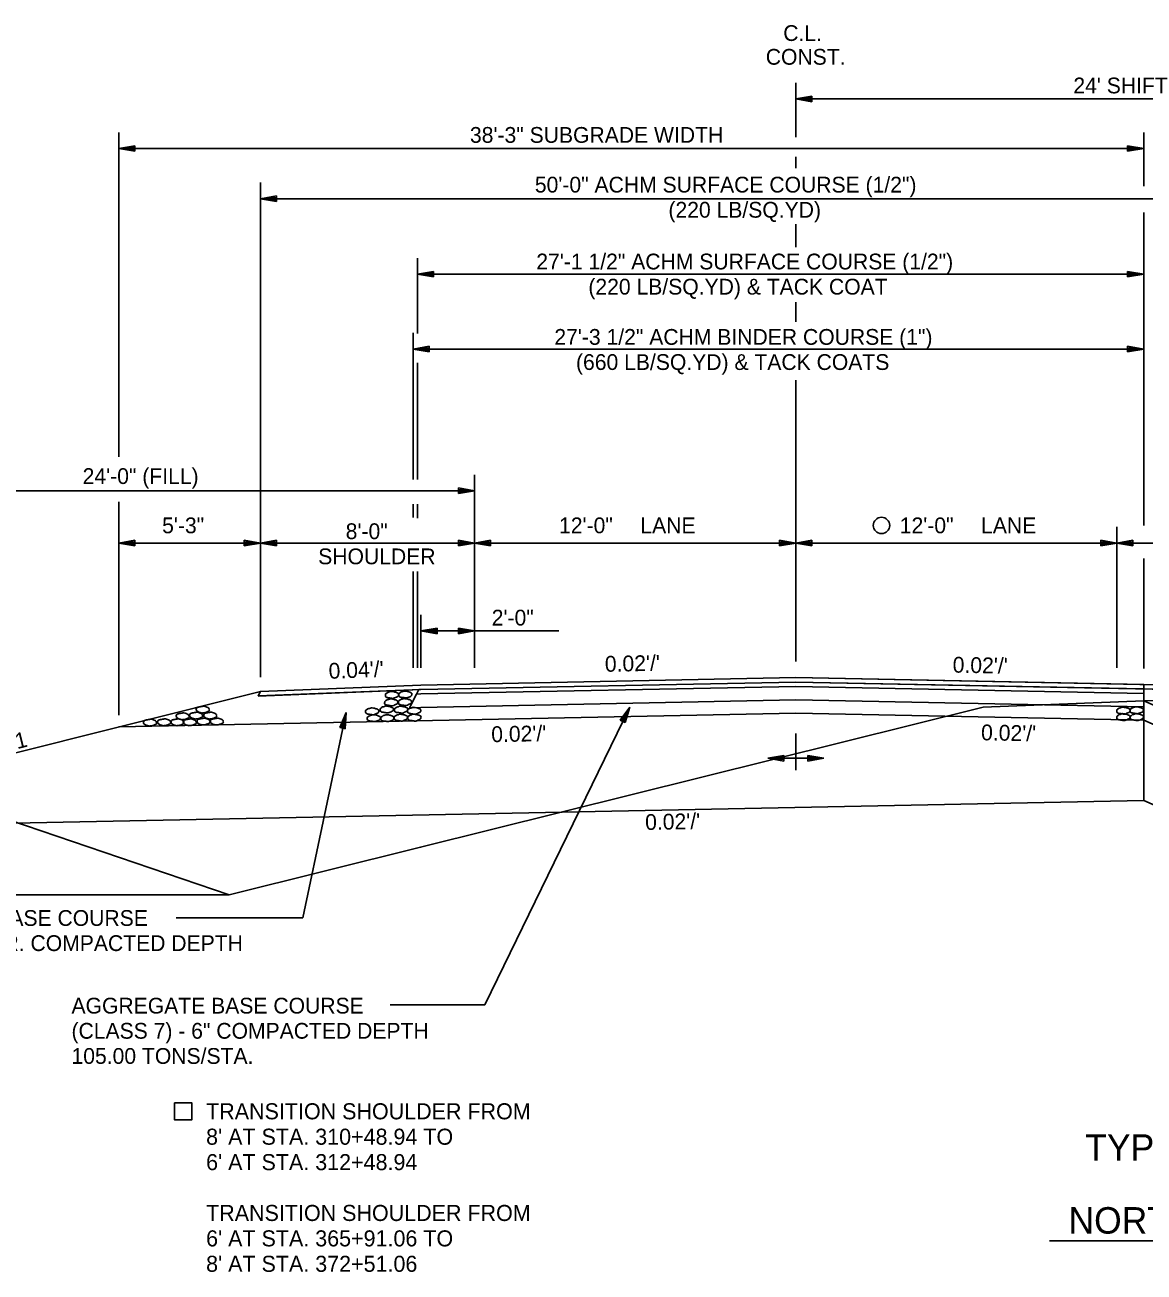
# Model space of a CAD drawing. Extents: x 1398565 to 1398920, y 1968324 to 1968581.
# Drawn here: x 1398801.17 to 1398842.98, y 1968479.92 to 1968526.53 of the extents above; entities that cross this region are included whole.
import ezdxf

# ---------------------------------------------------------------- set-up
doc = ezdxf.new("R2010")
doc.units = 0
for name, color, linetype in [('1', 7, 'Continuous'), ('10', 7, 'Continuous'), ('19', 7, 'Continuous'), ('42', 7, 'Continuous'), ('7', 7, 'Continuous'), ('Level 1', 7, 'Continuous')]:
    doc.layers.add(name, color=color, linetype=linetype)

# ---------------------------------------------------------------- blocks, each defined once
blk = doc.blocks.new('ROCKS')
at = {"layer": '1'}
blk.add_spline([(0.013, 0.06), (0.053, 0.053), (0.107, 0.033), (0.133, 0.013), (0.133, -0.007), (0.12, -0.033), (0.107, -0.04), (0.073, -0.053), (0.033, -0.067), (0.013, -0.067), (-0.02, -0.06), (-0.06, -0.053), (-0.087, -0.047), (-0.113, -0.02), (-0.113, -0.007), (-0.107, 0.02), (-0.087, 0.033), (-0.067, 0.047), (-0.033, 0.053), (-0.02, 0.06), (0.013, 0.06)], degree=3, dxfattribs=at)
blk = doc.blocks.new('4TO1 ABC')
at = {"layer": '1', "xscale": 0.1312491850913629, "yscale": 0.1312491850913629, "rotation": 180}
for p in [(0.00175, -0.00875), (-0.03325, -0.0385), (-0.016625, -0.023625), (0, -0.0385), (0.018375, -0.023625), (0.051625, -0.025375), (0.034125, -0.04025), (0.06475, -0.04025), (0.098, -0.04025), (0.133, -0.041125)]:
    blk.add_blockref('ROCKS', p, dxfattribs=at)

msp = doc.modelspace()

# ---------------------------------------------------------------- linework, layer by layer
at = {"layer": '10'}
msp.add_lwpolyline([(1398806.767, 1968486.248), (1398807.408, 1968486.248), (1398807.408, 1968485.607), (1398806.767, 1968485.607)], close=True, dxfattribs=at)
msp.add_circle((1398833.174, 1968507.826), 0.306, dxfattribs=at)
at = {"layer": '19'}
for p, q in [((1398830.569, 1968523.875), (1398829.969, 1968523.77)), ((1398853.969, 1968523.77), (1398829.969, 1968523.77)), ((1398829.969, 1968523.77), (1398830.569, 1968523.665)), ((1398830.569, 1968523.82), (1398830.129, 1968523.785)), ((1398830.129, 1968523.755), (1398830.569, 1968523.715)), ((1398830.569, 1968523.665), (1398830.569, 1968523.875)), ((1398804.684, 1968510.387), (1398804.684, 1968522.515)), ((1398842.969, 1968520.503), (1398842.969, 1968522.515)), ((1398805.284, 1968522.02), (1398804.684, 1968521.915)), ((1398842.969, 1968521.915), (1398804.684, 1968521.915)), ((1398804.684, 1968521.915), (1398805.284, 1968521.81)), ((1398805.284, 1968521.965), (1398804.844, 1968521.93)), ((1398804.844, 1968521.9), (1398805.284, 1968521.86)), ((1398805.284, 1968521.81), (1398805.284, 1968522.02)), ((1398842.369, 1968522.02), (1398842.369, 1968521.81)), ((1398842.969, 1968521.915), (1398842.369, 1968522.02)), ((1398842.809, 1968521.93), (1398842.369, 1968521.965)), ((1398842.369, 1968521.81), (1398842.969, 1968521.915)), ((1398842.369, 1968521.86), (1398842.809, 1968521.9)), ((1398809.969, 1968502.154), (1398809.969, 1968520.64)), ((1398810.569, 1968520.145), (1398809.969, 1968520.04)), ((1398809.969, 1968520.04), (1398859.969, 1968520.04)), ((1398809.969, 1968520.04), (1398810.569, 1968519.935)), ((1398810.569, 1968520.09), (1398810.129, 1968520.055)), ((1398810.129, 1968520.025), (1398810.569, 1968519.985)), ((1398810.569, 1968519.935), (1398810.569, 1968520.145)), ((1398842.969, 1968507.82), (1398842.969, 1968519.52)), ((1398815.842, 1968515.006), (1398815.842, 1968517.818)), ((1398816.442, 1968517.323), (1398815.842, 1968517.218)), ((1398815.842, 1968517.218), (1398816.442, 1968517.113)), ((1398815.842, 1968517.218), (1398842.969, 1968517.218)), ((1398816.442, 1968517.268), (1398816.002, 1968517.233)), ((1398816.002, 1968517.203), (1398816.442, 1968517.163)), ((1398816.442, 1968517.113), (1398816.442, 1968517.323)), ((1398842.369, 1968517.323), (1398842.369, 1968517.113)), ((1398842.969, 1968517.218), (1398842.369, 1968517.323)), ((1398842.809, 1968517.233), (1398842.369, 1968517.268)), ((1398842.369, 1968517.113), (1398842.969, 1968517.218)), ((1398842.369, 1968517.163), (1398842.809, 1968517.203)), ((1398815.672, 1968509.54), (1398815.672, 1968515.02)), ((1398816.272, 1968514.525), (1398815.672, 1968514.42)), ((1398815.672, 1968514.42), (1398842.969, 1968514.42)), ((1398815.672, 1968514.42), (1398816.272, 1968514.315)), ((1398816.272, 1968514.47), (1398815.832, 1968514.435)), ((1398815.832, 1968514.405), (1398816.272, 1968514.365)), ((1398816.272, 1968514.315), (1398816.272, 1968514.525)), ((1398842.369, 1968514.525), (1398842.369, 1968514.315)), ((1398842.969, 1968514.42), (1398842.369, 1968514.525)), ((1398842.809, 1968514.435), (1398842.369, 1968514.47)), ((1398842.369, 1968514.315), (1398842.969, 1968514.42)), ((1398842.369, 1968514.365), (1398842.809, 1968514.405)), ((1398815.842, 1968509.54), (1398815.842, 1968513.9)), ((1398817.969, 1968502.501), (1398817.969, 1968509.724)), ((1398793.969, 1968509.124), (1398817.969, 1968509.124)), ((1398817.369, 1968509.019), (1398817.369, 1968509.229)), ((1398817.369, 1968509.229), (1398817.969, 1968509.124)), ((1398817.369, 1968509.174), (1398817.809, 1968509.139)), ((1398817.969, 1968509.124), (1398817.369, 1968509.019)), ((1398804.684, 1968500.741), (1398804.684, 1968508.71)), ((1398817.809, 1968509.109), (1398817.369, 1968509.069)), ((1398815.672, 1968508.127), (1398815.672, 1968508.618)), ((1398815.842, 1968508.096), (1398815.842, 1968508.618)), ((1398841.969, 1968502.501), (1398841.969, 1968507.77)), ((1398804.684, 1968507.17), (1398805.284, 1968507.275)), ((1398805.284, 1968507.275), (1398805.284, 1968507.065)), ((1398809.369, 1968507.275), (1398809.369, 1968507.065)), ((1398809.969, 1968507.17), (1398809.369, 1968507.275)), ((1398809.969, 1968507.17), (1398810.569, 1968507.275)), ((1398810.569, 1968507.275), (1398810.569, 1968507.065)), ((1398817.369, 1968507.065), (1398817.369, 1968507.275)), ((1398817.369, 1968507.275), (1398817.969, 1968507.17)), ((1398817.969, 1968507.17), (1398818.569, 1968507.275)), ((1398818.569, 1968507.275), (1398818.569, 1968507.065)), ((1398829.369, 1968507.065), (1398829.369, 1968507.275)), ((1398829.369, 1968507.275), (1398829.969, 1968507.17)), ((1398829.969, 1968507.17), (1398830.569, 1968507.275)), ((1398830.569, 1968507.275), (1398830.569, 1968507.065)), ((1398841.369, 1968507.065), (1398841.369, 1968507.275)), ((1398841.369, 1968507.275), (1398841.969, 1968507.17)), ((1398841.969, 1968507.17), (1398842.569, 1968507.275)), ((1398842.569, 1968507.275), (1398842.569, 1968507.065)), ((1398859.969, 1968507.17), (1398804.684, 1968507.17)), ((1398805.284, 1968507.065), (1398804.684, 1968507.17)), ((1398804.844, 1968507.185), (1398805.284, 1968507.22)), ((1398805.284, 1968507.115), (1398804.844, 1968507.155)), ((1398809.809, 1968507.185), (1398809.369, 1968507.22)), ((1398809.369, 1968507.065), (1398809.969, 1968507.17)), ((1398809.369, 1968507.115), (1398809.809, 1968507.155)), ((1398810.569, 1968507.065), (1398809.969, 1968507.17)), ((1398810.129, 1968507.185), (1398810.569, 1968507.22)), ((1398810.569, 1968507.115), (1398810.129, 1968507.155)), ((1398817.369, 1968507.22), (1398817.809, 1968507.185)), ((1398817.969, 1968507.17), (1398817.369, 1968507.065)), ((1398817.809, 1968507.155), (1398817.369, 1968507.115)), ((1398818.569, 1968507.065), (1398817.969, 1968507.17)), ((1398818.129, 1968507.185), (1398818.569, 1968507.22)), ((1398818.569, 1968507.115), (1398818.129, 1968507.155)), ((1398829.369, 1968507.22), (1398829.809, 1968507.185)), ((1398829.969, 1968507.17), (1398829.369, 1968507.065)), ((1398829.809, 1968507.155), (1398829.369, 1968507.115)), ((1398830.569, 1968507.065), (1398829.969, 1968507.17)), ((1398830.129, 1968507.185), (1398830.569, 1968507.22)), ((1398830.569, 1968507.115), (1398830.129, 1968507.155)), ((1398841.369, 1968507.22), (1398841.809, 1968507.185)), ((1398841.969, 1968507.17), (1398841.369, 1968507.065)), ((1398841.809, 1968507.155), (1398841.369, 1968507.115)), ((1398842.569, 1968507.065), (1398841.969, 1968507.17)), ((1398842.129, 1968507.185), (1398842.569, 1968507.22)), ((1398842.569, 1968507.115), (1398842.129, 1968507.155)), ((1398842.969, 1968502.481), (1398842.969, 1968506.591)), ((1398815.672, 1968502.501), (1398815.672, 1968506.1)), ((1398815.842, 1968502.501), (1398815.842, 1968506.1)), ((1398815.969, 1968502.501), (1398815.969, 1968504.482)), ((1398815.969, 1968503.882), (1398816.569, 1968503.987)), ((1398815.969, 1968503.882), (1398821.116, 1968503.882)), ((1398816.569, 1968503.777), (1398815.969, 1968503.882)), ((1398816.129, 1968503.897), (1398816.569, 1968503.932)), ((1398816.569, 1968503.827), (1398816.129, 1968503.867)), ((1398816.569, 1968503.987), (1398816.569, 1968503.777)), ((1398817.369, 1968503.777), (1398817.369, 1968503.987)), ((1398817.369, 1968503.987), (1398817.969, 1968503.882)), ((1398817.369, 1968503.932), (1398817.809, 1968503.897)), ((1398817.969, 1968503.882), (1398817.369, 1968503.777)), ((1398817.809, 1968503.867), (1398817.369, 1968503.827)), ((1398829.969, 1968502.141), (1398815.969, 1968501.861)), ((1398829.969, 1968502.141), (1398855.969, 1968501.621)), ((1398815.969, 1968501.694), (1398809.884, 1968501.451)), ((1398815.969, 1968501.861), (1398809.969, 1968501.621)), ((1398815.884, 1968501.691), (1398815.799, 1968501.521)), ((1398829.969, 1968501.974), (1398815.969, 1968501.694)), ((1398829.969, 1968501.808), (1398815.969, 1968501.528)), ((1398829.969, 1968501.974), (1398855.969, 1968501.454)), ((1398829.969, 1968501.808), (1398842.969, 1968501.548)), ((1398842.969, 1968501.548), (1398829.969, 1968501.808)), ((1398842.969, 1968501.881), (1398842.969, 1968500.256)), ((1398809.969, 1968501.621), (1398793.969, 1968497.621)), ((1398809.969, 1968501.621), (1398809.884, 1968501.451)), ((1398815.799, 1968501.521), (1398815.544, 1968501.01)), ((1398815.969, 1968501.528), (1398815.799, 1968501.521)), ((1398829.969, 1968501.307), (1398815.969, 1968501.027)), ((1398829.969, 1968501.307), (1398842.969, 1968501.047)), ((1398829.969, 1968501.307), (1398842.969, 1968501.047)), ((1398842.969, 1968501.047), (1398842.969, 1968501.548)), ((1398842.969, 1968501.548), (1398842.969, 1968501.548)), ((1398842.969, 1968501.274), (1398845.712, 1968500.064)), ((1398829.969, 1968500.805), (1398804.684, 1968500.3)), ((1398811.552, 1968493.162), (1398813.172, 1968500.835)), ((1398813.172, 1968500.835), (1398812.937, 1968500.272)), ((1398813.141, 1968500.228), (1398813.172, 1968500.835)), ((1398815.969, 1968501.027), (1398815.544, 1968501.01)), ((1398818.351, 1968489.903), (1398823.771, 1968501.037)), ((1398823.771, 1968501.037), (1398823.408, 1968500.548)), ((1398823.689, 1968500.9), (1398823.456, 1968500.527)), ((1398823.551, 1968500.478), (1398823.714, 1968500.887)), ((1398823.595, 1968500.456), (1398823.771, 1968501.037)), ((1398829.969, 1968500.805), (1398842.969, 1968500.545)), ((1398812.937, 1968500.272), (1398813.141, 1968500.228)), ((1398813.125, 1968500.682), (1398812.99, 1968500.264)), ((1398813.093, 1968500.239), (1398813.152, 1968500.676)), ((1398823.408, 1968500.548), (1398823.595, 1968500.456)), ((1398842.969, 1968500.545), (1398845.712, 1968499.335)), ((1398842.969, 1968500.256), (1398842.969, 1968497.545)), ((1398842.969, 1968497.545), (1398790.6, 1968496.498)), ((1398842.969, 1968497.545), (1398845.712, 1968496.335)), ((1398806.824, 1968493.162), (1398811.552, 1968493.162)), ((1398814.823, 1968489.903), (1398818.351, 1968489.903)), ((1398839.453, 1968481.09), (1398868.433, 1968481.09))]:
    msp.add_line(p, q, dxfattribs=at)
for points in [[(1398809.887, 1968501.456), (1398815.969, 1968501.694), (1398829.969, 1968501.974), (1398855.969, 1968501.454), (1398860.054, 1968501.291), (1398859.969, 1968501.461), (1398855.969, 1968501.621), (1398829.969, 1968502.141), (1398815.969, 1968501.861), (1398809.969, 1968501.621)], [(1398815.884, 1968501.691), (1398815.799, 1968501.521), (1398815.969, 1968501.528), (1398829.969, 1968501.808), (1398842.969, 1968501.548), (1398842.969, 1968501.714), (1398829.969, 1968501.974), (1398815.969, 1968501.694)]]:
    msp.add_lwpolyline(points, close=True, dxfattribs=at)
for points in [[(1398829.969, 1968501.808), (1398815.969, 1968501.528), (1398815.799, 1968501.521), (1398815.544, 1968501.01)], [(1398815.544, 1968501.01), (1398815.969, 1968501.027), (1398829.969, 1968501.307)]]:
    msp.add_lwpolyline(points, dxfattribs=at)
at = {"layer": '42'}
for p, q in [((1398829.969, 1968500.046), (1398829.969, 1968498.675)), ((1398829.522, 1968499.232), (1398828.922, 1968499.127)), ((1398828.922, 1968499.127), (1398829.522, 1968499.022)), ((1398828.922, 1968499.127), (1398831.017, 1968499.127)), ((1398829.522, 1968499.177), (1398829.082, 1968499.142)), ((1398829.082, 1968499.112), (1398829.522, 1968499.072)), ((1398829.522, 1968499.022), (1398829.522, 1968499.232)), ((1398830.417, 1968499.022), (1398830.417, 1968499.232)), ((1398830.417, 1968499.232), (1398831.017, 1968499.127)), ((1398830.417, 1968499.177), (1398830.857, 1968499.142)), ((1398831.017, 1968499.127), (1398830.417, 1968499.022)), ((1398830.857, 1968499.112), (1398830.417, 1968499.072))]:
    msp.add_line(p, q, dxfattribs=at)
for points in [[(1398766.028, 1968494.02), (1398808.809, 1968494.02), (1398815.956, 1968495.8), (1398836.969, 1968501.034), (1398842.969, 1968501.274)], [(1398842.969, 1968501.274), (1398853.969, 1968501.494)], [(1398808.809, 1968494.02), (1398800.009, 1968497.014), (1398796.149, 1968497.696), (1398791.889, 1968498.539), (1398775.39, 1968500.448), (1398764.214, 1968500.493)]]:
    msp.add_lwpolyline(points, dxfattribs=at)
at = {"layer": '7'}
for p, q in [((1398829.969, 1968522.345), (1398829.969, 1968524.37)), ((1398829.969, 1968521.178), (1398829.969, 1968521.608)), ((1398829.969, 1968518.23), (1398829.969, 1968519.09)), ((1398829.969, 1968515.436), (1398829.969, 1968516.173)), ((1398829.969, 1968502.741), (1398829.969, 1968513.255))]:
    msp.add_line(p, q, dxfattribs=at)

# ---------------------------------------------------------------- block references
at = {"layer": '19', "xscale": 14.999970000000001, "yscale": -14.999970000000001, "rotation": 180}
msp.add_blockref('4TO1 ABC', (1398807.824, 1968501.068), dxfattribs=at)
at = {"layer": 'Level 1', "xscale": 2.011654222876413, "yscale": 2.011654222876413, "rotation": 1.8263814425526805}
for p in [(1398814.838, 1968501.218), (1398814.865, 1968501.497), (1398815.35, 1968501.23), (1398815.363, 1968501.512), (1398814.127, 1968500.883), (1398814.186, 1968500.627), (1398814.67, 1968500.953), (1398814.691, 1968500.627), (1398815.196, 1968500.648), (1398815.203, 1968500.948), (1398815.694, 1968500.905), (1398815.7, 1968500.647), (1398842.19, 1968500.91), (1398842.19, 1968500.668), (1398842.688, 1968500.924), (1398842.694, 1968500.667)]:
    msp.add_blockref('ROCKS', p, dxfattribs=at)

# ---------------------------------------------------------------- texts
at = {"layer": '10'}
for s, height, rotation, p in [('24\'-0" (FILL)', 0.59001, 360, (1398803.329, 1968509.376)), ('5\'-3"', 0.59, 360, (1398806.299, 1968507.534)), ('8\'-0" ', 0.59, 360, (1398813.156, 1968507.315)), ('12\'-0" ', 0.59, 360, (1398821.127, 1968507.534)), ('LANE', 0.59, 360, (1398824.165, 1968507.534)), ('12\'-0" ', 0.59, 360, (1398833.856, 1968507.534)), ('LANE', 0.59, 360, (1398836.894, 1968507.534)), ('SHOULDER', 0.59, 360, (1398812.129, 1968506.375)), ('2\'-0"', 0.59, 360, (1398818.612, 1968504.086)), ('4:1', 0.59, 13.7364, (1398800.242, 1968499.307))]:
    msp.add_text(s, height=height, rotation=rotation, dxfattribs=at).set_placement(p)
at = {"layer": '19'}
msp.add_text('C.L.', height=0.59, dxfattribs=at).set_placement((1398829.503, 1968525.935))
for s, height, rotation, p in [('CONST.', 0.59, 360, (1398828.85, 1968525.047)), ("24' SHIFT", 0.59, 360, (1398840.341, 1968523.976)), ("0.04'/'", 0.59, 2.2906, (1398812.53, 1968502.092)), ("0.02'/'", 0.59, 1.1458, (1398822.844, 1968502.355)), ("0.02'/'", 0.59, 358.8542, (1398835.828, 1968502.328)), ("0.02'/'", 0.59, 1.1458, (1398818.6, 1968499.725)), ("0.02'/'", 0.59, 358.8542, (1398836.889, 1968499.799)), ("0.02'/'", 0.59, 1.1458, (1398824.349, 1968496.442)), ('AGGREGATE BASE COURSE', 0.59001, 360, (1398794.849, 1968492.859)), ('(CLASS 7) - VAR. COMPACTED DEPTH', 0.59001, 360, (1398794.849, 1968491.919)), ('AGGREGATE BASE COURSE', 0.59001, 360, (1398802.913, 1968489.582)), ('(CLASS 7) - 6" COMPACTED DEPTH', 0.59001, 360, (1398802.913, 1968488.642)), ('105.00 TONS/STA.', 0.59001, 360, (1398802.913, 1968487.702)), ('TYPICAL SECTION OF IMPROVEMENT', 0.98999, 360, (1398840.787, 1968484.079)), ('NORTHBOUND PASSING LANE (SITE 3)', 0.98999, 360, (1398840.16, 1968481.356))]:
    msp.add_text(s, height=height, rotation=rotation, dxfattribs=at).set_placement(p)
at = {"layer": '42'}
for s, p in [('38\'-3" SUBGRADE WIDTH', (1398817.799, 1968522.128)), ('50\'-0" ACHM SURFACE COURSE (1/2")', (1398820.223, 1968520.27)), ('(220 LB/SQ.YD)', (1398825.213, 1968519.33)), ('27\'-1 1/2" ACHM SURFACE COURSE (1/2")', (1398820.278, 1968517.396)), ('(220 LB/SQ.YD) & TACK COAT', (1398822.222, 1968516.456)), ('27\'-3 1/2" ACHM BINDER COURSE (1")', (1398820.952, 1968514.578)), ('(660 LB/SQ.YD) & TACK COATS', (1398821.76, 1968513.638))]:
    msp.add_text(s, height=0.59001, rotation=360, dxfattribs=at).set_placement(p)
for s, p in [('TRANSITION SHOULDER FROM', (1398807.942, 1968485.629)), ("8' AT STA. 310+48.94 TO", (1398807.942, 1968484.679)), ("6' AT STA. 312+48.94", (1398807.942, 1968483.729)), ('TRANSITION SHOULDER FROM', (1398807.942, 1968481.829)), ("6' AT STA. 365+91.06 TO", (1398807.942, 1968480.879)), ("8' AT STA. 372+51.06", (1398807.942, 1968479.929))]:
    msp.add_text(s, height=0.6, dxfattribs=at).set_placement(p)

doc.saveas('drawing.dxf')
